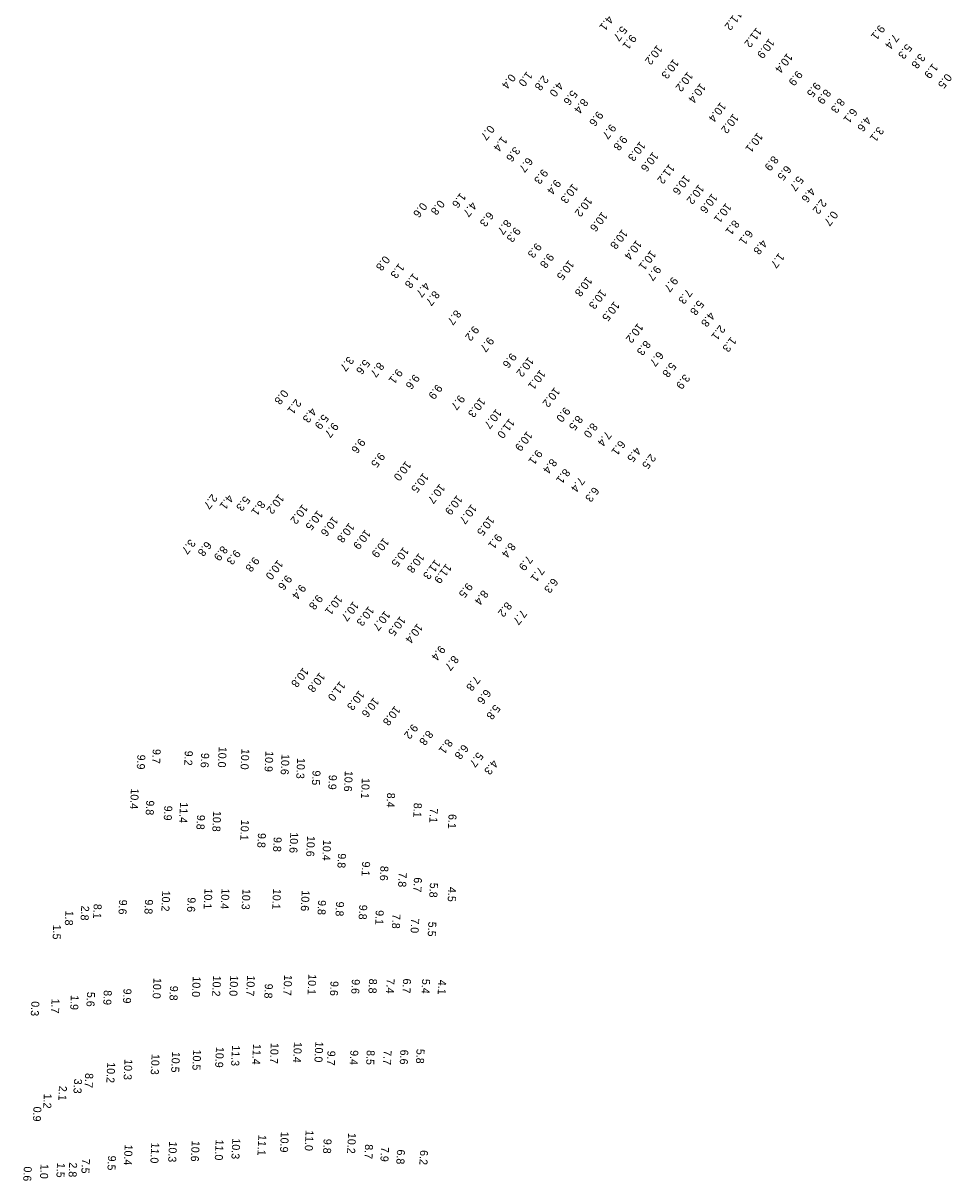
# Model space of a CAD drawing. Extents: x 815385 to 820851, y 582449 to 604245.
# Drawn here: x 817519 to 818099, y 601339 to 602062 of the extents above; entities that cross this region are included whole.
import ezdxf

# ---------------------------------------------------------------- set-up
doc = ezdxf.new("R2010")
doc.units = 0
doc.layers.add('V-TOPO-SOUN-022409', color=7, linetype='Continuous')

msp = doc.modelspace()

# ---------------------------------------------------------------- texts
at = {"layer": 'V-TOPO-SOUN-022409'}
for s, rotation, p in [('4.1', 232.428, (817884.4, 602067.21)), ('11.2 ', 232.428, (817964.87, 602070.43)), ('5.7', 232.428, (817893.01, 602060.71)), ('11.2 ', 232.428, (817977.2, 602059.69)), ('9.1', 232.428, (818054.02, 602061.43)), ('9.1', 232.428, (817898.84, 602055.45)), ('10.9 ', 232.428, (817985.11, 602052.85)), ('7.4', 232.428, (818062.79, 602055.71)), ('10.2 ', 232.428, (817915.13, 602048.85)), ('10.4 ', 232.428, (817996.41, 602043.74)), ('5.3', 232.428, (818070.96, 602049.57)), ('3.8', 232.428, (818079.27, 602043.51)), ('10.3 ', 232.428, (817925.37, 602040.09)), ('1.9', 232.428, (818087.25, 602037.33)), ('0.4', 232.428, (817823.38, 602030.88)), ('1.0', 232.428, (817833.86, 602032.31)), ('2.8', 232.428, (817843.94, 602029.83)), ('10.2 ', 232.428, (817934.2, 602032.12)), ('9.9', 232.428, (818002.52, 602032.83)), ('0.5', 232.428, (818095.83, 602031.07)), ('4.0', 232.428, (817853.22, 602025.88)), ('10.4 ', 232.428, (817942.21, 602024.95)), ('9.5', 232.428, (818013.95, 602025.65)), ('8.9', 232.428, (818020.3, 602021.34)), ('5.6', 232.428, (817861.97, 602020.66)), ('8.4', 232.428, (817868.65, 602015.46)), ('8.3', 232.428, (818028.93, 602015.7)), ('9.6', 232.428, (817878.03, 602007.53)), ('10.4 ', 232.428, (817954.78, 602013.09)), ('6.1', 232.428, (818036.81, 602009.41)), ('9.7', 232.428, (817886.11, 601999.52)), ('10.2 ', 232.428, (817962.69, 602005.94)), ('4.6', 232.428, (818045.45, 602004.22)), ('0.7', 232.428, (817810.2, 601998.8)), ('9.8', 232.428, (817893.11, 601992.31)), ('10.1 ', 232.428, (817977.84, 601994.09)), ('3.1', 232.428, (818053.33, 601997.82)), ('1.4', 232.428, (817818.19, 601991.74)), ('3.6', 232.428, (817826.15, 601985.36)), ('10.3 ', 232.428, (817904.47, 601988.58)), ('6.7', 232.428, (817834.11, 601978.67)), ('10.6 ', 232.428, (817912.54, 601982.01)), ('8.9', 232.428, (817987.52, 601979.63)), ('9.3', 232.428, (817843.59, 601971.36)), ('11.2 ', 232.428, (817922.78, 601974.48)), ('6.5', 232.428, (817995.56, 601973.64)), ('9.4', 232.428, (817851.66, 601964.86)), ('10.6 ', 232.428, (817932.38, 601967.62)), ('5.7', 232.428, (818003.22, 601967.01)), ('1.6', 232.428, (817792.34, 601956.49)), ('10.3 ', 232.428, (817862.39, 601962.24)), ('10.2 ', 232.428, (817941.15, 601961.72)), ('10.6 ', 232.428, (817949.46, 601956.08)), ('4.6', 232.428, (818010.61, 601959.86)), ('0.6', 232.428, (817768.07, 601950.49)), ('0.8', 232.428, (817779, 601952.03)), ('4.7', 232.428, (817799.18, 601950.91)), ('10.2 ', 232.428, (817871.25, 601953.9)), ('10.1 ', 232.428, (817958.18, 601950.09)), ('2.2', 232.428, (818017.6, 601952.61)), ('6.3', 232.428, (817809.65, 601944.75)), ('10.6 ', 232.428, (817880.76, 601944.63)), ('0.7', 232.428, (818024.66, 601945.24)), ('8.7', 232.428, (817820.66, 601939.84)), ('9.3', 232.428, (817826.42, 601935.07)), ('8.1', 232.428, (817963.13, 601939.54)), ('10.8 ', 232.428, (817893.37, 601933.65)), ('10.4 ', 232.428, (817902.23, 601926.97)), ('6.1', 232.428, (817971.6, 601933.41)), ('4.8', 232.428, (817980.54, 601927.31)), ('9.3', 232.428, (817839.57, 601925.22)), ('10.1 ', 232.428, (817911.16, 601920.55)), ('0.8', 232.428, (817744.8, 601917.21)), ('1.3', 232.428, (817753.89, 601912.39)), ('9.8', 232.428, (817847.26, 601918.76)), ('10.5 ', 232.428, (817859.97, 601914.36)), ('1.7', 232.428, (817991.27, 601918.87)), ('1.8', 232.428, (817762.84, 601906.3)), ('9.7', 232.428, (817914.18, 601911)), ('4.7', 232.428, (817769.83, 601900.69)), ('10.8 ', 232.428, (817871.26, 601904.07)), ('9.7', 232.428, (817924.8, 601904)), ('8.7', 232.428, (817775.85, 601895.35)), ('10.3 ', 232.428, (817880.03, 601896.18)), ('7.3', 232.428, (817933.67, 601896.43)), ('10.5 ', 232.428, (817888.32, 601888.64)), ('5.8', 232.428, (817940.99, 601889.39)), ('8.7', 232.428, (817789.34, 601883.33)), ('4.8', 232.428, (817947.87, 601882.13)), ('9.2', 232.428, (817800.49, 601873.39)), ('10.2 ', 232.428, (817903.13, 601875.03)), ('2.1', 232.428, (817954.33, 601873.85)), ('9.7', 232.428, (817809.81, 601866.44)), ('8.3', 232.428, (817907.72, 601864.31)), ('1.3', 232.428, (817961.29, 601866.45)), ('9.6', 232.428, (817823.94, 601856.44)), ('6.7', 232.428, (817915.74, 601857.44)), ('3.7', 232.428, (817722.34, 601854.36)), ('5.6', 232.428, (817732.38, 601852.42)), ('8.7', 232.428, (817741.23, 601850.67)), ('10.2 ', 232.428, (817834.79, 601853.88)), ('5.8', 232.428, (817923.69, 601850.61)), ('9.1', 232.428, (817752.78, 601846.53)), ('9.6', 232.428, (817763.35, 601843.17)), ('10.1 ', 232.428, (817842.07, 601845.88)), ('3.9', 232.428, (817932.26, 601843.23)), ('0.8', 232.428, (817681.35, 601833.59)), ('9.9', 232.428, (817777.59, 601836.9)), ('10.2 ', 232.428, (817851.11, 601834.92)), ('2.1', 232.428, (817689.5, 601827.64)), ('9.7', 232.428, (817791.63, 601830.24)), ('10.3 ', 232.428, (817804.56, 601828.51)), ('4.3', 232.428, (817699.01, 601822.24)), ('10.7 ', 232.428, (817814.64, 601821.48)), ('9.0', 232.428, (817857.47, 601822.64)), ('5.9', 232.428, (817706.55, 601818.15)), ('9.7', 232.428, (817712.7, 601812.98)), ('11.0 ', 232.428, (817822.85, 601815.44)), ('8.5', 232.428, (817865.33, 601817.45)), ('8.0', 232.428, (817874.54, 601812.79)), ('10.9 ', 232.428, (817833.91, 601807.47)), ('7.4', 232.428, (817883.2, 601807.52)), ('9.6', 232.428, (817729.44, 601803.08)), ('6.1', 232.428, (817891.93, 601801.86)), ('4.5', 232.428, (817901.72, 601797.68)), ('9.5', 232.428, (817741.71, 601794.25)), ('9.1', 232.428, (817840.08, 601795.99)), ('8.4', 232.428, (817849.17, 601790.44)), ('2.5', 232.428, (817910.99, 601793.39)), ('10.0 ', 232.428, (817758.18, 601788.87)), ('8.1', 232.428, (817857.4, 601784.2)), ('10.5 ', 232.428, (817769.06, 601781.48)), ('7.4', 232.428, (817866.53, 601778.92)), ('2.7', 232.428, (817637.11, 601768.32)), ('4.1', 232.428, (817647.17, 601768)), ('10.2 ', 232.428, (817678.79, 601768.17)), ('10.7 ', 232.428, (817779.37, 601774.63)), ('10.9 ', 232.428, (817790.18, 601767.59)), ('6.3', 232.428, (817875.53, 601772.76)), ('5.3', 232.428, (817657.51, 601767.06)), ('8.1', 232.428, (817666.95, 601764.28)), ('10.2 ', 232.428, (817693.64, 601761.85)), ('10.7 ', 232.428, (817799.18, 601761.92)), ('10.5 ', 232.428, (817703.04, 601758.05)), ('10.6 ', 232.428, (817712.56, 601754.24)), ('10.5 ', 232.428, (817810.13, 601754.51)), ('10.8 ', 232.428, (817722.72, 601750.24)), ('10.9 ', 232.428, (817732.87, 601746.09)), ('3.7', 232.428, (817623.41, 601740.11)), ('10.9 ', 232.428, (817744.31, 601740.87)), ('9.1', 232.428, (817814.93, 601743.45)), ('6.8', 232.428, (817633.47, 601738.8)), ('8.9', 232.428, (817643.53, 601735.97)), ('9.3', 232.428, (817651.52, 601733.54)), ('10.5 ', 232.428, (817756.72, 601735.13)), ('8.4', 232.428, (817823.34, 601737.94)), ('9.8', 232.428, (817663.29, 601729.08)), ('10.0 ', 232.428, (817678.19, 601727.1)), ('10.8 ', 232.428, (817766.39, 601731.34)), ('11.3 ', 232.428, (817776.49, 601727.32)), ('11.9 ', 232.428, (817783.42, 601724.74)), ('7.9', 232.428, (817834.03, 601729.83)), ('9.6', 232.428, (817683.62, 601717.72)), ('7.1', 232.428, (817841.35, 601722.76)), ('9.4', 232.428, (817692.41, 601711.94)), ('9.5', 232.428, (817796.52, 601712.86)), ('6.3', 232.428, (817849.87, 601715.83)), ('9.8', 232.428, (817702.91, 601705.42)), ('10.1 ', 232.428, (817715.25, 601705.11)), ('8.4', 232.428, (817806.34, 601708.34)), ('10.7 ', 232.428, (817725.41, 601701.2)), ('10.3 ', 232.428, (817734.97, 601698.19)), ('10.7 ', 232.428, (817745.08, 601695.3)), ('8.2', 232.428, (817820.99, 601700.92)), ('7.7', 232.428, (817830.36, 601696.01)), ('10.5 ', 232.428, (817754.71, 601691.97)), ('10.4 ', 232.428, (817765.42, 601687.39)), ('9.4', 232.428, (817779.47, 601673.62)), ('8.7', 232.428, (817787.8, 601667.4)), ('10.8 ', 232.428, (817694.1, 601659.88)), ('10.8 ', 232.428, (817704.38, 601656.79)), ('7.8', 232.428, (817801.19, 601654.64)), ('11.0 ', 232.428, (817717.02, 601651.28)), ('10.3 ', 232.428, (817728.96, 601645.51)), ('6.6', 232.428, (817808, 601646.37)), ('10.6 ', 232.428, (817738.14, 601641.14)), ('10.8 ', 232.428, (817751.39, 601635.95)), ('5.8', 232.428, (817813.78, 601636.8)), ('9.2', 232.428, (817762.35, 601624.65)), ('8.8', 232.428, (817771.85, 601620.67)), ('9.7', 267.255, (817600.14, 601608.74)), ('10.0 ', 267.255, (817641.33, 601610.11)), ('10.0 ', 267.255, (817655.55, 601608.82)), ('8.1', 232.428, (817784.01, 601615.29)), ('6.8', 232.428, (817793.94, 601611.93)), ('9.9', 267.255, (817590.54, 601605.22)), ('9.2', 267.255, (817620.19, 601607.65)), ('9.6', 267.255, (817630.41, 601606.26)), ('10.9 ', 267.255, (817670.53, 601607.39)), ('10.6 ', 267.255, (817680.6, 601605.57)), ('10.3 ', 267.255, (817690.34, 601603.09)), ('5.7', 232.428, (817803.2, 601607.04)), ('4.3', 232.428, (817812.41, 601602.31)), ('9.5', 267.255, (817699.95, 601595.32)), ('10.6 ', 267.255, (817720.12, 601595.09)), ('9.9', 267.255, (817710.16, 601592.57)), ('10.1 ', 267.255, (817730.74, 601590.58)), ('10.4 ', 267.255, (817586.5, 601584.09)), ('8.4', 267.255, (817746.53, 601581.38)), ('9.8', 267.255, (817596.11, 601576.63)), ('9.9', 267.255, (817607.38, 601573.3)), ('11.4 ', 267.255, (817617.19, 601575.41)), ('8.1', 267.255, (817763.22, 601575.1)), ('9.8', 267.255, (817627.8, 601567.56)), ('10.8 ', 267.255, (817637.91, 601570.02)), ('7.1', 267.255, (817773.25, 601571.74)), ('6.1', 267.255, (817784.9, 601568.07)), ('10.1 ', 267.255, (817655.34, 601564.46)), ('9.8', 267.255, (817665.85, 601556.24)), ('9.8', 267.255, (817675.69, 601553.74)), ('10.6 ', 267.255, (817686.05, 601556.67)), ('10.6 ', 267.255, (817696.52, 601554.41)), ('10.4 ', 267.255, (817706.58, 601551.95)), ('9.8', 267.255, (817715.87, 601543.55)), ('9.1', 267.255, (817730.94, 601538.42)), ('8.6', 267.255, (817742.34, 601535.65)), ('7.8', 267.255, (817753.79, 601531.63)), ('6.7', 267.255, (817763.29, 601528.5)), ('5.8', 267.255, (817773.27, 601525.14)), ('4.5', 267.255, (817784.73, 601522.52)), ('9.6', 267.255, (817579.13, 601514.58)), ('9.8', 267.255, (817595.31, 601514.75)), ('10.2 ', 267.255, (817606.09, 601520.22)), ('9.6', 267.255, (817621.95, 601516.05)), ('10.1 ', 267.255, (817632.49, 601521.59)), ('10.4 ', 267.255, (817643.14, 601521.62)), ('10.3 ', 267.255, (817656.21, 601521.29)), ('10.1 ', 267.255, (817675.31, 601521.35)), ('10.6 ', 267.255, (817693.17, 601520.38)), ('1.8', 267.255, (817545.59, 601507.67)), ('2.8', 267.255, (817555.47, 601510.84)), ('8.1', 267.255, (817563.26, 601511.98)), ('9.8', 267.255, (817703.44, 601514.31)), ('9.8', 267.255, (817714.67, 601513.41)), ('9.8', 267.255, (817729.14, 601511.38)), ('9.1', 267.255, (817739.46, 601508.04)), ('7.8', 267.255, (817749.87, 601505.7)), ('7.0', 267.255, (817761.57, 601502.93)), ('5.5', 267.255, (817772.26, 601500.78)), ('1.5', 267.255, (817537.98, 601498.95)), ('10.0 ', 267.255, (817600.59, 601465.69)), ('10.0 ', 267.255, (817625.14, 601466.64)), ('10.2 ', 267.255, (817637.81, 601467.11)), ('10.0 ', 267.255, (817648.55, 601467.25)), ('10.7 ', 267.255, (817659.02, 601467.24)), ('10.7 ', 267.255, (817682.23, 601467.62)), ('10.1 ', 267.255, (817697.39, 601468.02)), ('9.6', 267.255, (817724.52, 601464.91)), ('8.8', 267.255, (817735.26, 601465.19)), ('7.4', 267.255, (817746.2, 601465.19)), ('6.7', 267.255, (817756.49, 601465.29)), ('5.4', 267.255, (817768.39, 601465.06)), ('4.1', 267.255, (817778.5, 601464.5)), ('5.6', 267.255, (817559.09, 601456.94)), ('8.9', 267.255, (817569.59, 601458.02)), ('9.9', 267.255, (817581.89, 601459.03)), ('9.8', 267.255, (817610.97, 601460.78)), ('9.8', 267.255, (817670.19, 601462.13)), ('9.6', 267.255, (817711.18, 601463.74)), ('0.3', 267.255, (817524.33, 601451.09)), ('1.7', 267.255, (817536.97, 601452.72)), ('1.9', 267.255, (817548.97, 601454.93)), ('10.5 ', 267.255, (817625.44, 601420.91)), ('10.9 ', 267.255, (817639.64, 601422.59)), ('11.3 ', 267.255, (817649.67, 601423.59)), ('11.4 ', 267.255, (817662.78, 601424.42)), ('10.7 ', 267.255, (817673.85, 601425.05)), ('10.4 ', 267.255, (817688.34, 601425.64)), ('10.0 ', 267.255, (817701.69, 601425.92)), ('9.4', 267.255, (817723.57, 601420.55)), ('8.5', 267.255, (817733.83, 601420.58)), ('7.7', 267.255, (817744.32, 601420.53)), ('6.6', 267.255, (817754.81, 601420.86)), ('5.8', 267.255, (817764.93, 601421.37)), ('10.3 ', 267.255, (817582.49, 601414.93)), ('10.3 ', 267.255, (817599.45, 601418.17)), ('10.5 ', 267.255, (817612.19, 601419.54)), ('9.7', 267.255, (817709.25, 601420.22)), ('8.7', 267.255, (817557.99, 601406.23)), ('10.2 ', 267.255, (817571.73, 601413.01)), ('3.3', 267.255, (817550.99, 601402.67)), ('1.2', 267.255, (817532.11, 601393.36)), ('2.1', 267.255, (817541.56, 601398.25)), ('0.9', 267.255, (817525.62, 601385.26)), ('11.0 ', 267.255, (817695.62, 601370.58)), ('11.0 ', 267.255, (817599.22, 601362.82)), ('10.3 ', 267.255, (817610.33, 601363.48)), ('10.6 ', 267.255, (817624.47, 601363.91)), ('11.0 ', 267.255, (817639.43, 601364.68)), ('10.3 ', 267.255, (817649.84, 601365.43)), ('11.1 ', 267.255, (817666.09, 601367.63)), ('10.9 ', 267.255, (817680.17, 601369.62)), ('9.8', 267.255, (817706.86, 601365.16)), ('10.2 ', 267.255, (817722.11, 601368.84)), ('10.4 ', 267.255, (817582.61, 601361.57)), ('8.7', 267.255, (817732.75, 601361.76)), ('7.9', 267.255, (817742.72, 601360.11)), ('6.8', 267.255, (817752.69, 601358.48)), ('6.2', 267.255, (817767.08, 601358.09)), ('1.0', 267.255, (817530.09, 601349.44)), ('1.5', 267.255, (817540.34, 601350.14)), ('2.8', 267.255, (817547.94, 601350.41)), ('7.5', 267.255, (817555.92, 601352.72)), ('9.5', 267.255, (817572.22, 601354.68)), ('0.6', 267.255, (817519.62, 601347.88))]:
    msp.add_text(s, height=5, rotation=rotation, dxfattribs=at).set_placement(p)

doc.saveas('drawing.dxf')
